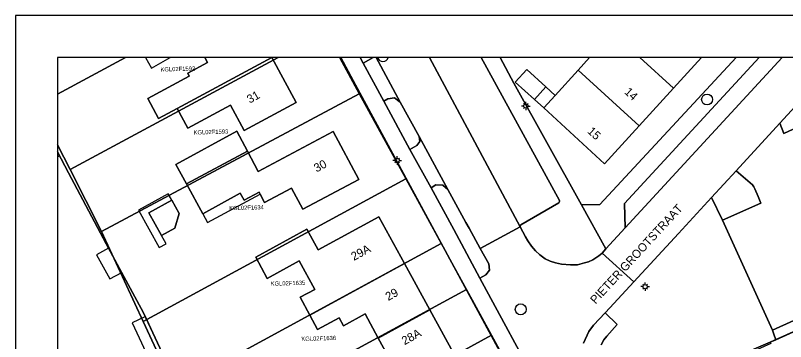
# Model space of a CAD drawing. Extents: x 124901 to 125496, y 515369 to 515789.
# Drawn here: x 124901.4 to 124992.7, y 515750.4 to 515789 of the extents above; entities that cross this region are included whole.
import ezdxf

# ---------------------------------------------------------------- set-up
doc = ezdxf.new("R2010")
doc.units = 0
for name, color, linetype in [('Alg Kaders', 7, 'Continuous'), ('Gebouw', 7, 'Continuous'), ('Inrit', 7, 'Continuous'), ('Kunstwerkdeel', 7, 'Continuous'), ('Lichtmast', 7, 'Continuous'), ('Luifel', 7, 'Continuous'), ('Onbegroeid terrein', 7, 'Continuous'), ('Parkeren', 7, 'Continuous'), ('Perceelnummers', 7, 'Continuous'), ('Perceelsgrenzen', 7, 'Continuous'), ('Putten', 7, 'Continuous'), ('Scheiding', 7, 'Continuous'), ('Teksten', 7, 'Continuous'), ('Vegetatie', 7, 'Continuous'), ('Voetpad', 7, 'Continuous'), ('Water', 7, 'Continuous'), ('Wegen drempel verkeerseiland', 7, 'Continuous'), ('Wegen lokale weg', 7, 'Continuous')]:
    doc.layers.add(name, color=color, linetype=linetype)

msp = doc.modelspace()

# ---------------------------------------------------------------- linework, layer by layer
at = {"layer": 'Alg Kaders'}
for points in [[(125495.925, 515789.043), (124901.425, 515789.043), (124901.425, 515368.543), (125495.925, 515368.543)], [(125490.925, 515784.043), (124906.425, 515784.043), (124906.425, 515373.543), (125490.925, 515373.543)]]:
    msp.add_lwpolyline(points, close=True, dxfattribs=at)
at = {"layer": 'Gebouw'}
for points in [[(124923.89, 515784.043), (124924.201, 515783.464), (124921.847, 515782.198), (124922.039, 515781.841), (124917.13, 515779.2), (124918.402, 515776.834), (124920.59, 515778.01), (124931.805, 515784.043)], [(124919.765, 515784.043), (124919.767, 515784.039), (124919.774, 515784.043)], [(124931.805, 515784.043), (124920.59, 515778.01), (124921.846, 515775.676), (124926.922, 515778.407), (124928.539, 515775.401), (124934.692, 515778.712), (124931.824, 515784.043)], [(124969.488, 515784.043), (124968.131, 515782.555), (124975.373, 515775.952), (124979.443, 515780.415), (124975.464, 515784.043)], [(124975.464, 515784.043), (124979.443, 515780.415), (124982.75, 515784.043)]]:
    msp.add_lwpolyline(points, dxfattribs=at)
for points in [[(124962.957, 515779.066), (124964.31, 515780.552), (124962.033, 515782.625), (124960.681, 515781.138)], [(124975.373, 515775.952), (124968.131, 515782.555), (124965.399, 515779.559), (124964.045, 515778.074), (124971.274, 515771.456)], [(124928.923, 515772.943), (124927.662, 515775.308), (124920.453, 515771.371), (124921.697, 515769.077)], [(124942.138, 515769.597), (124939.098, 515775.282), (124930.216, 515770.532), (124928.923, 515772.943), (124921.697, 515769.077), (124923.626, 515765.526), (124928.081, 515767.943), (124928.531, 515767.114), (124930.307, 515768.077), (124930.426, 515767.854), (124930.969, 515766.84), (124934.158, 515768.546), (124935.496, 515766.045)], [(124919.973, 515767.133), (124917.26, 515765.636), (124918.757, 515762.922), (124920.333, 515763.792), (124920.842, 515765.557)], [(124936.331, 515753.491), (124947.546, 515759.624), (124944.521, 515765.156), (124937.328, 515761.223), (124935.979, 515763.69), (124929.929, 515760.38), (124931.287, 515757.82), (124935.06, 515759.949), (124936.917, 515756.554), (124935.196, 515755.613)], [(124947.546, 515759.624), (124936.331, 515753.491), (124937.249, 515751.775), (124939.809, 515753.189), (124940.328, 515752.224), (124942.874, 515753.639), (124944.438, 515750.778), (124950.554, 515754.123)], [(124992.435, 515746.875), (124993.918, 515743.588), (125010.345, 515750.999), (125010.741, 515751.178), (125007.723, 515757.866), (124991.566, 515750.577), (124990.9, 515750.276), (124990.969, 515750.123), (124987.796, 515748.689), (124989.253, 515745.345)], [(124947.447, 515745.277), (124953.563, 515748.622), (124950.554, 515754.123), (124944.438, 515750.778), (124947.203, 515745.723)]]:
    msp.add_lwpolyline(points, close=True, dxfattribs=at)
at = {"layer": 'Inrit'}
msp.add_lwpolyline([(124943.821, 515784.043), (124942.649, 515783.359), (124945.084, 515778.876), (124945.566, 515779.152), (124946.378, 515779.254), (124947.02, 515778.748), (124944.199, 515784.043)], dxfattribs=at)
msp.add_lwpolyline([(124948.178, 515773.131), (124950.72, 515768.609), (124951.262, 515768.941), (124952.073, 515768.92), (124952.683, 515768.386), (124949.285, 515774.682), (124949.357, 515774.095), (124949.001, 515773.623)], close=True, dxfattribs=at)
at = {"layer": 'Kunstwerkdeel'}
msp.add_lwpolyline([(124906.425, 515772.286), (124906.662, 515772.411), (124906.425, 515772.874)], dxfattribs=at)
for points in [[(124911.032, 515760.663), (124912.62, 515757.782), (124914.033, 515758.561), (124912.466, 515761.454)], [(124915.267, 515752.592), (124917.728, 515747.339), (124919.268, 515748.061), (124916.832, 515753.326)]]:
    msp.add_lwpolyline(points, close=True, dxfattribs=at)
at = {"layer": 'Lichtmast'}
for p, q in [((124961.632, 515778.297), (124961.432, 515778.296)), ((124961.72, 515778.084), (124961.648, 515778.013)), ((124961.72, 515778.508), (124961.65, 515778.579)), ((124961.932, 515778.596), (124961.932, 515778.796)), ((124962.144, 515778.508), (124962.215, 515778.58)), ((124962.144, 515778.084), (124962.214, 515778.013)), ((124962.232, 515778.296), (124962.432, 515778.296)), ((124961.932, 515777.996), (124961.932, 515777.796)), ((124946.378, 515771.837), (124946.178, 515771.836)), ((124946.466, 515771.624), (124946.394, 515771.553)), ((124946.466, 515772.048), (124946.396, 515772.119)), ((124946.678, 515772.136), (124946.678, 515772.336)), ((124946.89, 515772.048), (124946.961, 515772.12)), ((124946.89, 515771.624), (124946.96, 515771.553)), ((124946.978, 515771.836), (124947.178, 515771.836)), ((124946.678, 515771.536), (124946.678, 515771.336)), ((124975.86, 515757.087), (124975.79, 515757.158)), ((124976.072, 515757.175), (124976.072, 515757.375)), ((124976.284, 515757.087), (124976.355, 515757.159)), ((124975.772, 515756.876), (124975.572, 515756.875)), ((124975.86, 515756.663), (124975.788, 515756.592)), ((124976.072, 515756.575), (124976.072, 515756.375)), ((124976.284, 515756.663), (124976.354, 515756.592)), ((124976.372, 515756.875), (124976.572, 515756.875))]:
    msp.add_line(p, q, dxfattribs=at)
for centre in [(124961.932, 515778.296), (124946.678, 515771.836), (124976.072, 515756.875)]:
    msp.add_circle(centre, 0.25, dxfattribs=at)
at = {"layer": 'Luifel'}
msp.add_lwpolyline([(124916.862, 515784.043), (124917.557, 515782.801), (124919.767, 515784.039), (124919.765, 515784.043)], dxfattribs=at)
for points in [[(124962.957, 515779.066), (124964.045, 515778.074), (124965.399, 515779.559), (124964.31, 515780.552)], [(124928.081, 515767.943), (124923.626, 515765.526), (124924.181, 515764.494), (124930.426, 515767.854), (124930.307, 515768.077), (124928.531, 515767.114)], [(124919.973, 515767.133), (124919.553, 515767.894), (124916.019, 515765.945), (124918.471, 515761.499), (124919.292, 515761.952), (124918.757, 515762.922), (124917.26, 515765.636)]]:
    msp.add_lwpolyline(points, close=True, dxfattribs=at)
at = {"layer": 'Onbegroeid terrein'}
for points in [[(124931.824, 515784.043), (124934.692, 515778.712), (124928.539, 515775.401), (124926.922, 515778.407), (124921.846, 515775.676), (124920.59, 515778.01), (124918.402, 515776.834), (124917.13, 515779.2), (124922.039, 515781.841), (124921.847, 515782.198), (124924.201, 515783.464), (124923.89, 515784.043)], [(124919.774, 515784.043), (124919.767, 515784.039), (124919.765, 515784.043)], [(124962.015, 515743.343), (124941.47, 515781.335), (124940.01, 515784.043)], [(124958.906, 515784.043), (124960.528, 515780.995), (124968.528, 515766.596), (124970.719, 515766.604), (124986.858, 515784.043)], [(124982.75, 515784.043), (124979.443, 515780.415), (124975.373, 515775.952), (124971.274, 515771.456), (124964.045, 515778.074), (124965.399, 515779.559), (124968.131, 515782.555), (124969.488, 515784.043)], [(124906.425, 515772.874), (124907.707, 515770.367), (124912.198, 515761.95), (124916.618, 515753.787), (124920.468, 515745.467)], [(124947.203, 515745.723), (124944.438, 515750.778), (124942.874, 515753.639), (124940.328, 515752.224), (124939.809, 515753.189), (124937.249, 515751.775), (124936.331, 515753.491), (124935.196, 515755.613), (124936.917, 515756.554), (124935.06, 515759.949), (124931.287, 515757.82), (124929.929, 515760.38), (124935.979, 515763.69), (124937.328, 515761.223), (124944.521, 515765.156), (124947.546, 515759.624), (124950.554, 515754.123), (124953.563, 515748.622)]]:
    msp.add_lwpolyline(points, dxfattribs=at)
for points in [[(124964.31, 515780.552), (124962.957, 515779.066), (124960.681, 515781.138), (124962.033, 515782.625)], [(124939.098, 515775.282), (124942.138, 515769.597), (124935.496, 515766.045), (124934.158, 515768.546), (124930.969, 515766.84), (124930.426, 515767.854), (124930.307, 515768.077), (124928.531, 515767.114), (124928.081, 515767.943), (124923.626, 515765.526), (124921.697, 515769.077), (124920.453, 515771.371), (124927.662, 515775.308), (124928.923, 515772.943), (124930.216, 515770.532)], [(124917.26, 515765.636), (124919.973, 515767.133), (124920.842, 515765.557), (124920.333, 515763.792), (124918.757, 515762.922)]]:
    msp.add_lwpolyline(points, close=True, dxfattribs=at)
at = {"layer": 'Parkeren'}
for points in [[(124942.277, 515784.043), (124942.649, 515783.359), (124943.821, 515784.043)], [(124950.509, 515784.043), (124961.267, 515763.977), (124961.272, 515764.055), (124961.291, 515764.139), (124961.344, 515764.218), (124965.86, 515766.814), (124965.898, 515766.876), (124965.922, 515766.97), (124965.909, 515767.097), (124956.647, 515784.043)], [(124989.583, 515784.043), (124973.639, 515766.739), (124973.703, 515763.832), (124992.334, 515784.043)], [(124996.713, 515776.986), (124992.5, 515775.048), (124992.026, 515776.243), (124986.863, 515770.613), (124988.784, 515768.931), (124988.957, 515768.697), (124989.08, 515768.493), (124989.464, 515767.557), (124989.785, 515766.773), (124985.246, 515764.75), (124991.17, 515751.711), (125000, 515755.693)]]:
    msp.add_lwpolyline(points, dxfattribs=at)
at = {"layer": 'Perceelsgrenzen'}
for p, q in [((124906.425, 515779.686), (124914.47, 515784.043)), ((124914.47, 515784.043), (124906.425, 515779.686))]:
    msp.add_line(p, q, dxfattribs=at)
for points in [[(124932.583, 515784.043), (124907.898, 515770.764), (124906.425, 515773.675)], [(124939.831, 515784.043), (124942.181, 515779.749), (124911.623, 515763.401), (124907.898, 515770.764), (124932.583, 515784.043)], [(124939.831, 515784.043), (124942.181, 515779.749), (124947.7, 515769.665), (124951.905, 515761.983), (124954.881, 515756.546), (124957.852, 515751.118), (124962.459, 515742.701), (124967.05, 515734.312), (124970.025, 515728.876), (124974.299, 515721.067), (124978.481, 515713.427), (124980.664, 515709.438), (124982.132, 515705.346), (124982.796, 515703.495), (124984.315, 515694.743), (124982.043, 515693.067), (124980.61, 515692.413), (124979.086, 515692.308), (124948.888, 515690.522), (124946.892, 515695.063), (124949.333, 515679.527)], [(124906.425, 515773.675), (124907.898, 515770.764), (124911.623, 515763.401), (124916.573, 515752.754), (124918.909, 515747.729), (124920.514, 515744.921), (124923.602, 515739.522), (124926.526, 515733.933), (124930.887, 515725.594), (124935.308, 515717.138), (124935.342, 515717.073), (124938.219, 515711.628), (124939.11, 515709.943), (124942.106, 515703.52), (124943.454, 515700.593), (124931.273, 515695.979), (124906.425, 515742.864)]]:
    msp.add_lwpolyline(points, dxfattribs=at)
for points in [[(124988.906, 515713.205), (124972.893, 515742.592), (124990.9, 515750.276), (125007.671, 515757.842), (125002.477, 515769.567), (125026.186, 515779.978), (125040.828, 515746.88), (125037.558, 515745.497), (125057.095, 515701.642), (125041.951, 515699.428), (124992.815, 515699.484), (124991.996, 515704.137), (124990.673, 515708.803), (124990.18, 515710.264)], [(124947.7, 515769.665), (124916.573, 515752.754), (124911.623, 515763.401), (124942.181, 515779.749)], [(124947.7, 515769.665), (124951.905, 515761.983), (124920.514, 515744.921), (124918.909, 515747.729), (124916.573, 515752.754)], [(124951.905, 515761.983), (124954.881, 515756.546), (124923.602, 515739.522), (124920.514, 515744.921)], [(124972.893, 515742.592), (124988.906, 515713.205), (124990.18, 515710.264), (124990.673, 515708.803), (124991.996, 515704.137), (124992.815, 515699.484), (125041.951, 515699.428), (125057.095, 515701.642), (125037.558, 515745.497), (125037.493, 515745.642), (125024.246, 515739.7), (125017.617, 515754.699), (125013.263, 515760.497), (125007.723, 515757.866), (125007.671, 515757.842), (124990.9, 515750.276)], [(124954.881, 515756.546), (124957.852, 515751.118), (124926.526, 515733.933), (124923.602, 515739.522)], [(124926.526, 515733.933), (124957.852, 515751.118), (124962.459, 515742.701), (124930.887, 515725.594)]]:
    msp.add_lwpolyline(points, close=True, dxfattribs=at)
at = {"layer": 'Putten'}
for centre in [(124983.42, 515779.07), (124961.33, 515754.18)]:
    msp.add_circle(centre, 0.65, dxfattribs=at)
msp.add_arc((124944.99, 515784.22), 0.65, 195.80163, 344.19837, dxfattribs=at)
at = {"layer": 'Scheiding'}
for points in [[(124912.467, 515761.454), (124912.198, 515761.95), (124907.707, 515770.367), (124906.662, 515772.41)], [(124916.832, 515753.325), (124916.618, 515753.787), (124914.033, 515758.561)]]:
    msp.add_lwpolyline(points, dxfattribs=at)
at = {"layer": 'Vegetatie'}
for points in [[(125000, 515780.848), (125000.375, 515781.012), (125000.159, 515781.371), (125000, 515781.558), (124999.669, 515781.946), (124999.191, 515782.337), (124998.277, 515783.039), (124995.191, 515779.695), (124992.026, 515776.243), (124992.5, 515775.048), (124996.713, 515776.986), (124995.859, 515779.039)], [(124948.178, 515773.131), (124949.001, 515773.623), (124949.357, 515774.095), (124949.285, 515774.682), (124947.02, 515778.748), (124946.378, 515779.254), (124945.566, 515779.152), (124945.084, 515778.876)], [(124991.566, 515750.577), (125007.723, 515757.866), (125002.673, 515769.453), (125005.279, 515770.613), (125004.12, 515773.116), (125000, 515771.204), (124999.684, 515771.057), (125000, 515770.344), (125005.411, 515758.133), (125000, 515755.693), (124991.17, 515751.711), (124991.337, 515751.231)], [(124989.464, 515767.557), (124989.08, 515768.493), (124988.957, 515768.697), (124988.784, 515768.931), (124986.863, 515770.613), (124983.953, 515767.44), (124985.246, 515764.75), (124989.785, 515766.773)], [(124952.683, 515768.386), (124952.073, 515768.92), (124951.262, 515768.941), (124950.72, 515768.609), (124953.377, 515763.659), (124956.475, 515757.887), (124957.174, 515758.27), (124957.629, 515758.837), (124957.549, 515759.56), (124956.534, 515761.402), (124955.197, 515763.827), (124954.834, 515764.484)]]:
    msp.add_lwpolyline(points, close=True, dxfattribs=at)
msp.add_lwpolyline([(124990.9, 515750.276), (124991.566, 515750.577), (124991.337, 515751.231), (124991.17, 515751.711), (124985.246, 515764.75), (124983.953, 515767.44), (124980.042, 515763.175), (124974.745, 515757.464), (124971.877, 515754.373), (124971.325, 515753.784), (124972.743, 515752.365), (124971.513, 515750.989), (124971.166, 515750.557), (124970.855, 515749.979)], dxfattribs=at)
at = {"layer": 'Voetpad'}
for points in [[(124940.01, 515784.043), (124941.47, 515781.335), (124962.015, 515743.343)], [(124963.703, 515744.533), (124956.475, 515757.887), (124953.377, 515763.659), (124950.72, 515768.609), (124948.178, 515773.131), (124945.084, 515778.876), (124942.649, 515783.359), (124942.277, 515784.043)], [(124956.647, 515784.043), (124965.909, 515767.097), (124965.922, 515766.97), (124965.898, 515766.876), (124965.86, 515766.814), (124961.344, 515764.218), (124961.291, 515764.139), (124961.272, 515764.055), (124961.267, 515763.977), (124961.898, 515762.789), (124962.176, 515762.295), (124962.598, 515761.672), (124963.081, 515761.13), (124963.602, 515760.643), (124964.206, 515760.184), (124964.808, 515759.912), (124965.456, 515759.68), (124966.168, 515759.546), (124967.239, 515759.468), (124968.047, 515759.463), (124968.89, 515759.704), (124969.345, 515759.826), (124969.872, 515760.058), (124970.595, 515760.538), (124970.984, 515760.863), (124971.42, 515761.339), (124968.528, 515766.596), (124960.528, 515780.995), (124958.906, 515784.043)], [(124986.858, 515784.043), (124970.719, 515766.604), (124968.528, 515766.596), (124971.42, 515761.339), (124973.703, 515763.832), (124973.639, 515766.739), (124989.583, 515784.043)], [(124970.855, 515749.979), (124971.166, 515750.557), (124971.513, 515750.989), (124972.743, 515752.365), (124971.325, 515753.784), (124969.946, 515752.312), (124969.402, 515751.548), (124968.772, 515750.169)]]:
    msp.add_lwpolyline(points, dxfattribs=at)
at = {"layer": 'Water'}
msp.add_lwpolyline([(124920.468, 515745.467), (124916.618, 515753.787), (124912.198, 515761.95), (124907.707, 515770.367), (124906.425, 515772.874)], dxfattribs=at)
at = {"layer": 'Wegen drempel verkeerseiland'}
msp.add_lwpolyline([(124968.772, 515750.169), (124969.402, 515751.548), (124969.946, 515752.312), (124971.325, 515753.784), (124971.877, 515754.373), (124974.745, 515757.464), (124970.984, 515760.863), (124970.595, 515760.538), (124969.872, 515760.058), (124969.345, 515759.826), (124968.89, 515759.704), (124968.047, 515759.463), (124967.239, 515759.468), (124966.168, 515759.546), (124965.456, 515759.68), (124964.808, 515759.912), (124964.206, 515760.184), (124963.602, 515760.643), (124963.081, 515761.13), (124962.598, 515761.672), (124962.176, 515762.295), (124961.898, 515762.789), (124961.267, 515763.977), (124956.534, 515761.402), (124957.549, 515759.56), (124957.629, 515758.837), (124957.174, 515758.27), (124956.475, 515757.887), (124963.703, 515744.533)], dxfattribs=at)
at = {"layer": 'Wegen lokale weg'}
for points in [[(124944.199, 515784.043), (124947.02, 515778.748), (124949.285, 515774.682), (124952.683, 515768.386), (124954.834, 515764.484), (124955.197, 515763.827), (124956.534, 515761.402), (124961.267, 515763.977), (124950.509, 515784.043)], [(124992.334, 515784.043), (124973.703, 515763.832), (124971.42, 515761.339), (124970.984, 515760.863), (124974.745, 515757.464), (124980.042, 515763.175), (124983.953, 515767.44), (124986.863, 515770.613), (124992.026, 515776.243), (124995.191, 515779.695), (124998.277, 515783.039), (124999.204, 515784.043)]]:
    msp.add_lwpolyline(points, dxfattribs=at)

# ---------------------------------------------------------------- texts
at = {"layer": 'Perceelnummers'}
for s, rotation, p in [('KGL02F1592', 1.62891, (124918.631, 515782.382)), ('KGL02F1593', 1.62895, (124922.555, 515774.909)), ('KGL02F1634', 1.629, (124926.776, 515765.933)), ('KGL02F1635', 1.62906, (124931.693, 515756.974)), ('KGL02F1636', 1.6291, (124935.331, 515750.434))]:
    msp.add_text(s, height=0.5, rotation=rotation, dxfattribs=at).set_placement(p)
at = {"layer": 'Teksten'}
for s, rotation, p in [('31', 29.2, (124929.206, 515778.57)), ('14', 317.6, (124973.535, 515779.863)), ('15', 317.5, (124969.154, 515775.194)), ('30', 28.1, (124937.127, 515770.41)), ('PIETER GROOTSTRAAT', 47.4, (124970.192, 515754.747)), ('29A', 28.7, (124941.551, 515759.921)), ('29', 28.7, (124945.615, 515755.161)), ('28A', 28.7, (124947.551, 515749.921))]:
    msp.add_text(s, height=1, rotation=rotation, dxfattribs=at).set_placement(p)

doc.saveas('drawing.dxf')
